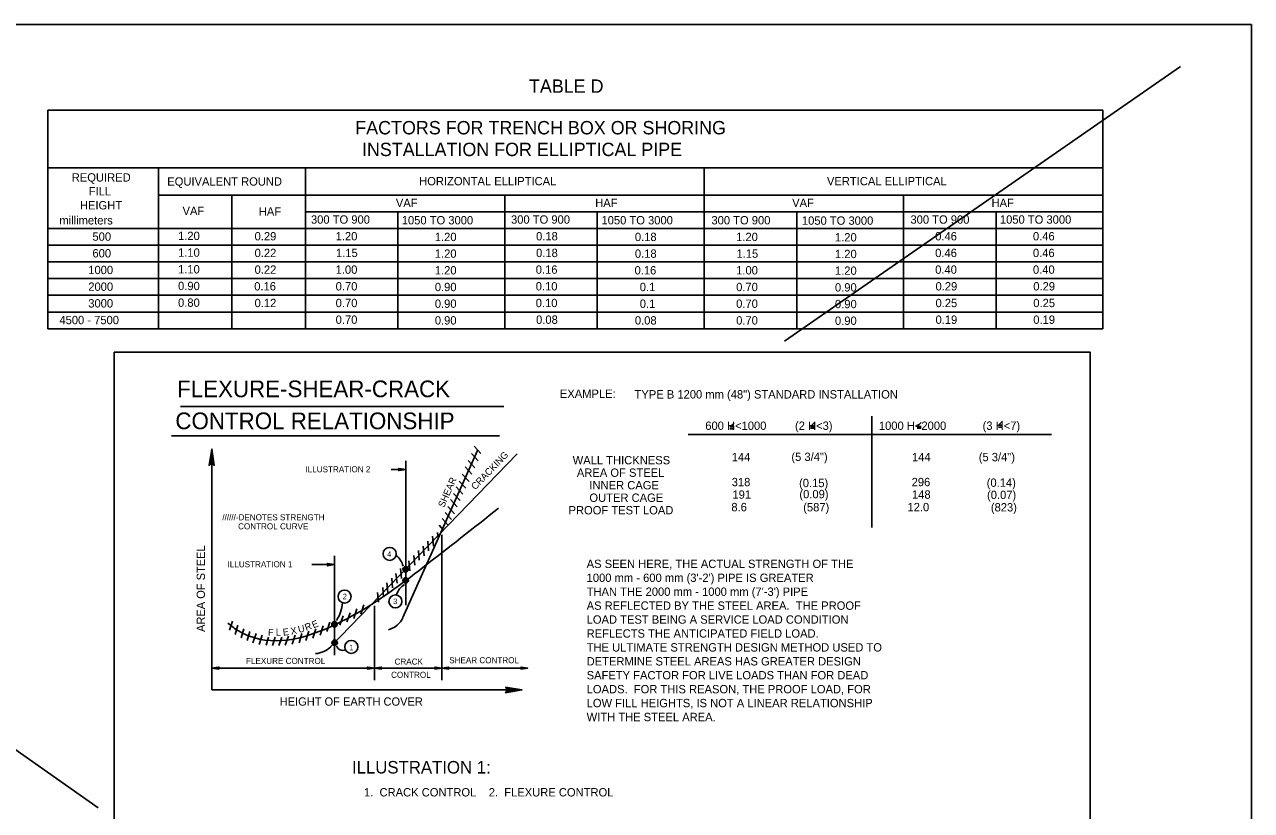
# Model space of a CAD drawing. Extents: x -22562 to -18409, y 3991 to 7171.
# Drawn here: x -21681.6 to -21240.8, y 6069.8 to 6352.4 of the extents above; entities that cross this region are included whole.
import ezdxf

# ---------------------------------------------------------------- set-up
doc = ezdxf.new("R2010")
doc.units = 0
for name, color, linetype in [('1', 7, 'Continuous'), ('2', 7, 'Continuous'), ('Default', 7, 'Continuous')]:
    doc.layers.add(name, color=color, linetype=linetype)

msp = doc.modelspace()

# ---------------------------------------------------------------- linework, layer by layer
at = {"layer": '1'}
for p, q in [((-22026.85, 6352.37), (-21240.85, 6352.37)), ((-21633.47, 6291.02), (-21294.22, 6291.02)), ((-21607.1, 6291.02), (-21607.1, 6243.02)), ((-21547.47, 6285.02), (-21547.47, 6243.02)), ((-21475.85, 6285.02), (-21475.85, 6243.02)), ((-21404.22, 6285.02), (-21404.22, 6243.02)), ((-21332.6, 6285.02), (-21332.6, 6243.02))]:
    msp.add_line(p, q, dxfattribs=at)
at = {"layer": '2'}
for p, q in [((-21240.85, 6352.37), (-21240.85, 5788.37)), ((-21673.22, 6321.56), (-21294.22, 6321.56)), ((-21673.22, 6321.56), (-21673.22, 6243.02)), ((-21294.22, 6321.56), (-21294.22, 6243.02)), ((-21673.22, 6300.83), (-21294.22, 6300.83)), ((-21633.47, 6300.83), (-21633.47, 6243.02)), ((-21580.72, 6300.83), (-21580.72, 6243.02)), ((-21437.47, 6300.83), (-21437.47, 6243.02)), ((-21509.1, 6291.02), (-21509.1, 6243.02)), ((-21365.85, 6291.02), (-21365.85, 6243.02)), ((-21580.72, 6285.02), (-21294.22, 6285.02)), ((-21673.22, 6279.02), (-21294.22, 6279.02)), ((-21673.22, 6273.02), (-21294.22, 6273.02)), ((-21673.22, 6267.02), (-21294.22, 6267.02)), ((-21673.22, 6261.02), (-21294.22, 6261.02)), ((-21673.22, 6255.02), (-21294.22, 6255.02)), ((-21673.22, 6249.02), (-21294.22, 6249.02)), ((-21673.22, 6243.02), (-21294.22, 6243.02)), ((-21509.44, 6215.02), (-21625.56, 6215.02)), ((-21377.17, 6211.56), (-21377.17, 6171.58)), ((-21426.7, 6209.2), (-21428.2, 6207.7)), ((-21428.2, 6207.7), (-21426.7, 6207.7)), ((-21428.2, 6207.08), (-21426.7, 6207.08)), ((-21397.73, 6209.37), (-21399.23, 6207.87)), ((-21399.23, 6207.87), (-21397.73, 6207.87)), ((-21399.23, 6207.25), (-21397.73, 6207.25)), ((-21359.46, 6209.33), (-21360.96, 6207.83)), ((-21360.96, 6207.83), (-21359.46, 6207.83)), ((-21360.96, 6207.21), (-21359.46, 6207.21)), ((-21330.24, 6209.8), (-21331.74, 6208.3)), ((-21331.74, 6208.3), (-21330.24, 6208.3)), ((-21331.74, 6207.68), (-21330.24, 6207.68)), ((-21510.94, 6204.52), (-21628.81, 6204.52)), ((-21443.19, 6204.96), (-21312.63, 6204.96)), ((-21614.31, 6199.77), (-21614.31, 6113.15)), ((-21571.56, 6128.77), (-21504.69, 6198.02)), ((-21545.69, 6139.15), (-21518.94, 6199.27)), ((-21521.06, 6198.15), (-21518.69, 6195.52)), ((-21520.06, 6200.77), (-21517.69, 6198.15)), ((-21544.69, 6195.52), (-21544.69, 6143.65)), ((-21523.31, 6193.4), (-21520.94, 6190.77)), ((-21522.19, 6195.65), (-21519.81, 6193.02)), ((-21549.94, 6192.4), (-21544.69, 6192.4)), ((-21524.44, 6190.77), (-21521.94, 6188.15)), ((-21526.56, 6186.15), (-21524.19, 6183.52)), ((-21525.44, 6188.27), (-21523.06, 6185.65)), ((-21528.56, 6181.65), (-21526.19, 6179.02)), ((-21527.56, 6183.77), (-21525.06, 6181.27)), ((-21530.56, 6176.9), (-21528.19, 6174.4)), ((-21529.56, 6179.15), (-21527.19, 6176.52)), ((-21532.69, 6172.4), (-21531.06, 6170.65)), ((-21531.56, 6174.77), (-21529.44, 6172.4)), ((-21536.69, 6166.65), (-21536.44, 6163.15)), ((-21535.06, 6168.4), (-21534.69, 6164.9)), ((-21533.31, 6169.77), (-21533.06, 6167.4)), ((-21531.69, 6168.9), (-21531.69, 6116.65)), ((-21540.06, 6163.27), (-21539.81, 6159.77)), ((-21538.44, 6164.9), (-21538.06, 6161.4)), ((-21578.44, 6158.27), (-21570.31, 6158.27)), ((-21570.31, 6161.4), (-21570.31, 6125.65)), ((-21543.56, 6159.52), (-21543.19, 6156.02)), ((-21541.81, 6161.52), (-21541.44, 6158.02)), ((-21549.69, 6153.4), (-21549.44, 6149.9)), ((-21548.19, 6155.02), (-21547.81, 6151.52)), ((-21546.56, 6156.77), (-21546.19, 6153.27)), ((-21552.94, 6150.02), (-21552.69, 6146.52)), ((-21551.44, 6151.65), (-21551.06, 6148.15)), ((-21554.81, 6148.15), (-21554.44, 6144.77)), ((-21564.69, 6140.9), (-21565.81, 6137.65)), ((-21562.19, 6142.27), (-21563.31, 6138.9)), ((-21559.69, 6143.77), (-21560.81, 6140.4)), ((-21555.94, 6143.4), (-21555.94, 6116.65)), ((-21606.94, 6137.9), (-21607.94, 6134.65)), ((-21604.94, 6136.4), (-21605.94, 6133.15)), ((-21574.31, 6136.27), (-21575.44, 6132.9)), ((-21571.94, 6137.52), (-21573.06, 6134.15)), ((-21567.19, 6139.77), (-21568.31, 6136.4)), ((-21602.81, 6135.15), (-21603.81, 6131.9)), ((-21600.69, 6134.15), (-21601.69, 6130.9)), ((-21598.44, 6133.4), (-21599.56, 6130.15)), ((-21596.19, 6132.9), (-21597.31, 6129.52)), ((-21593.94, 6132.15), (-21594.81, 6129.27)), ((-21591.56, 6132.15), (-21592.56, 6129.15)), ((-21589.19, 6132.15), (-21590.31, 6129.15)), ((-21586.81, 6132.52), (-21587.94, 6129.27)), ((-21584.44, 6132.9), (-21585.44, 6129.65)), ((-21581.94, 6133.4), (-21582.94, 6130.15)), ((-21579.44, 6134.27), (-21580.56, 6130.9)), ((-21576.94, 6135.15), (-21578.06, 6131.77)), ((-21614.31, 6121.02), (-21555.94, 6121.02)), ((-21555.94, 6121.02), (-21531.69, 6121.02)), ((-21531.69, 6121.02), (-21500.81, 6121.02)), ((-21614.31, 6113.15), (-21502.94, 6113.15))]:
    msp.add_line(p, q, dxfattribs=at)
for points in [[(-21615.06, 6194.15), (-21614.69, 6194.27), (-21614.31, 6199.77), (-21615.06, 6194.15), (-21615.31, 6193.9), (-21614.31, 6199.77), (-21614.06, 6194.4), (-21613.69, 6194.15), (-21614.31, 6199.77), (-21613.44, 6193.9), (-21613.69, 6194.15)], [(-21547.06, 6192.65), (-21547.06, 6192.52), (-21544.69, 6192.4), (-21547.06, 6192.65), (-21547.19, 6192.77), (-21544.69, 6192.4), (-21547.06, 6192.27), (-21547.06, 6192.02), (-21544.69, 6192.4), (-21547.19, 6192.02), (-21547.06, 6192.02)], [(-21572.69, 6158.52), (-21572.56, 6158.4), (-21570.31, 6158.27), (-21572.69, 6158.52), (-21572.81, 6158.65), (-21570.31, 6158.27), (-21572.56, 6158.15), (-21572.69, 6157.9), (-21570.31, 6158.27), (-21572.81, 6157.77), (-21572.69, 6157.9)], [(-21611.94, 6120.77), (-21612.06, 6120.9), (-21614.31, 6121.02), (-21611.94, 6120.77), (-21611.81, 6120.65), (-21614.31, 6121.02), (-21612.06, 6121.15), (-21611.94, 6121.4), (-21614.31, 6121.02), (-21611.81, 6121.4), (-21611.94, 6121.4)], [(-21558.31, 6121.4), (-21558.19, 6121.15), (-21555.94, 6121.02), (-21558.31, 6121.4), (-21558.44, 6121.4), (-21555.94, 6121.02), (-21558.19, 6120.9), (-21558.31, 6120.77), (-21555.94, 6121.02), (-21558.44, 6120.65), (-21558.31, 6120.77)], [(-21553.56, 6120.77), (-21553.69, 6120.9), (-21555.94, 6121.02), (-21553.56, 6120.77), (-21553.44, 6120.65), (-21555.94, 6121.02), (-21553.69, 6121.15), (-21553.56, 6121.4), (-21555.94, 6121.02), (-21553.44, 6121.4), (-21553.56, 6121.4)], [(-21534.06, 6121.4), (-21533.94, 6121.15), (-21531.69, 6121.02), (-21534.06, 6121.4), (-21534.19, 6121.4), (-21531.69, 6121.02), (-21533.94, 6120.9), (-21534.06, 6120.77), (-21531.69, 6121.02), (-21534.19, 6120.65), (-21534.06, 6120.77)], [(-21529.31, 6120.77), (-21529.44, 6120.9), (-21531.69, 6121.02), (-21529.31, 6120.77), (-21529.19, 6120.65), (-21531.69, 6121.02), (-21529.44, 6121.15), (-21529.31, 6121.4), (-21531.69, 6121.02), (-21529.19, 6121.4), (-21529.31, 6121.4)], [(-21503.19, 6121.4), (-21503.19, 6121.15), (-21500.81, 6121.02), (-21503.19, 6121.4), (-21503.31, 6121.4), (-21500.81, 6121.02), (-21503.19, 6120.9), (-21503.19, 6120.77), (-21500.81, 6121.02), (-21503.31, 6120.65), (-21503.19, 6120.77)], [(-21508.56, 6113.9), (-21508.31, 6113.4), (-21502.94, 6113.15), (-21508.56, 6113.9), (-21508.81, 6114.15), (-21502.94, 6113.15), (-21508.31, 6112.9), (-21508.56, 6112.52), (-21502.94, 6113.15), (-21508.81, 6112.15), (-21508.56, 6112.52)]]:
    msp.add_lwpolyline(points, dxfattribs=at)
for centre, radius in [((-21550.44, 6162.08), 2.35), ((-21544.72, 6156.54), 0.976), ((-21544.68, 6152.55), 0.976), ((-21544.72, 6156.54), 0.804), ((-21544.68, 6152.55), 0.778), ((-21544.72, 6156.54), 0.6), ((-21544.72, 6156.54), 0.4), ((-21544.72, 6156.54), 0.175), ((-21566.63, 6146.73), 2.35), ((-21544.68, 6152.55), 0.574), ((-21544.68, 6152.55), 0.326), ((-21544.68, 6152.55), 0.147), ((-21548.37, 6145.01), 2.35), ((-21570.28, 6136.78), 0.976), ((-21570.28, 6136.78), 0.826), ((-21570.28, 6136.78), 0.6), ((-21570.28, 6136.78), 0.38), ((-21570.28, 6136.78), 0.189), ((-21570.21, 6130.15), 0.976), ((-21570.21, 6130.15), 0.755), ((-21570.21, 6130.15), 0.538), ((-21570.21, 6130.15), 0.302), ((-21570.21, 6130.15), 0.14), ((-21564.22, 6128.63), 2.35)]:
    msp.add_circle(centre, radius, dxfattribs=at)
for centre, radius, start, end in [((-21552.67, 6155.84), 7.29, 14.6383, 49.5671), ((-21541.42, 6145.31), 6.88, 122.2525, 163.6384), ((-21581.55, 6145.71), 14.19, 327.6246, 355.0838), ((-21553.08, 6142.64), 8.17, 286.1711, 334.5647), ((-21577.94, 6135.49), 9.32, 275.4083, 313.415), ((-21567.24, 6129.86), 2.46, 199.0809, 292.6529)]:
    msp.add_arc(centre, radius, start, end, dxfattribs=at)
msp.add_spline([(-21608.56, 6137.15), (-21604.81, 6134.4), (-21589.19, 6130.9), (-21575.56, 6134.27), (-21550.44, 6148.27), (-21538.56, 6157.15), (-21511.31, 6178.52)], degree=3, dxfattribs=at)
at = {"layer": 'Default'}
for p, q in [((-22043.04, 6343.98), (-21655.17, 6070.76)), ((-21408.57, 6238.49), (-21266.39, 6337.22))]:
    msp.add_line(p, q, dxfattribs=at)
msp.add_lwpolyline([(-21649.46, 6234.6), (-21298.83, 6234.6), (-21298.83, 5958.1), (-21649.46, 5958.1)], close=True, dxfattribs=at)

# ---------------------------------------------------------------- texts
at = {"layer": '1'}
for s, height, p in [('TABLE D', 4.806, (-21500.41, 6327.82)), ('FACTORS FOR TRENCH BOX OR SHORING', 4.8057, (-21562.8, 6312.88)), ('INSTALLATION FOR ELLIPTICAL PIPE', 4.8057, (-21560.39, 6305.07)), ('EQUIVALENT ROUND', 3, (-21630.35, 6294.45)), ('HORIZONTAL ELLIPTICAL', 3, (-21539.85, 6294.57)), ('VERTICAL ELLIPTICAL', 3, (-21393.35, 6294.57)), ('VAF', 3, (-21624.85, 6283.89)), ('HAF', 3, (-21597.47, 6283.64)), ('VAF', 3, (-21548.22, 6286.77)), ('HAF', 3, (-21476.6, 6286.77)), ('VAF', 3, (-21405.85, 6286.77)), ('HAF', 3, (-21334.22, 6286.77)), ('300 TO 900', 3, (-21578.72, 6280.77)), ('1050 TO 3000', 3, (-21546.1, 6280.52)), ('300 TO 900', 3, (-21506.85, 6280.77)), ('1050 TO 3000', 3, (-21474.35, 6280.52)), ('300 TO 900', 3, (-21434.85, 6280.52)), ('1050 TO 3000', 3, (-21402.35, 6280.39)), ('300 TO 900', 3, (-21363.35, 6280.77)), ('1050 TO 3000', 3, (-21331.22, 6280.77)), ('1.20', 3, (-21626.47, 6274.89)), ('0.29', 3, (-21598.97, 6274.77)), ('1.20', 3, (-21569.85, 6274.77)), ('1.20', 3, (-21534.22, 6274.52)), ('0.18', 3, (-21497.85, 6274.77)), ('0.18', 3, (-21462.35, 6274.52)), ('1.20', 3, (-21425.97, 6274.52)), ('1.20', 3, (-21390.47, 6274.39)), ('0.46', 3, (-21354.47, 6274.77)), ('0.46', 3, (-21319.35, 6274.77)), ('1.10', 3, (-21626.47, 6268.89)), ('0.22', 3, (-21598.97, 6268.77)), ('1.15', 3, (-21569.72, 6268.77)), ('1.20', 3, (-21534.22, 6268.52)), ('0.18', 3, (-21497.85, 6268.77)), ('0.18', 3, (-21462.35, 6268.52)), ('1.15', 3, (-21425.85, 6268.52)), ('1.20', 3, (-21390.47, 6268.39)), ('0.46', 3, (-21354.47, 6268.77)), ('0.46', 3, (-21319.35, 6268.77)), ('1.10', 3, (-21626.47, 6262.89)), ('0.22', 3, (-21598.97, 6262.77)), ('1.00', 3, (-21569.85, 6262.77)), ('1.20', 3, (-21534.22, 6262.52)), ('0.16', 3, (-21497.97, 6262.77)), ('0.16', 3, (-21462.47, 6262.52)), ('1.00', 3, (-21425.97, 6262.52)), ('1.20', 3, (-21390.47, 6262.39)), ('0.40', 3, (-21354.47, 6262.77)), ('0.40', 3, (-21319.35, 6262.77)), ('0.90', 3, (-21626.47, 6256.89)), ('0.16', 3, (-21599.1, 6256.77)), ('0.70', 3, (-21569.85, 6256.77)), ('0.90', 3, (-21534.22, 6256.52)), ('0.10', 3, (-21497.97, 6256.77)), ('0.1', 3, (-21460.6, 6256.52)), ('0.70', 3, (-21425.97, 6256.52)), ('0.90', 3, (-21390.47, 6256.39)), ('0.29', 3, (-21354.35, 6256.77)), ('0.29', 3, (-21319.22, 6256.77)), ('0.80', 3, (-21626.47, 6250.89)), ('0.12', 3, (-21598.97, 6250.77)), ('0.70', 3, (-21569.85, 6250.77)), ('0.90', 3, (-21534.22, 6250.52)), ('0.10', 3, (-21497.97, 6250.77)), ('0.1', 3, (-21460.6, 6250.52)), ('0.70', 3, (-21425.97, 6250.52)), ('0.90', 3, (-21390.47, 6250.39)), ('0.25', 3, (-21354.35, 6250.77)), ('0.25', 3, (-21319.22, 6250.77)), ('0.70', 3, (-21569.85, 6244.77)), ('0.90', 3, (-21534.22, 6244.52)), ('0.08', 3, (-21497.85, 6244.77)), ('0.08', 3, (-21462.35, 6244.52)), ('0.70', 3, (-21425.97, 6244.52)), ('0.90', 3, (-21390.47, 6244.39)), ('0.19', 3, (-21354.35, 6244.77)), ('0.19', 3, (-21319.22, 6244.77))]:
    msp.add_text(s, height=height, dxfattribs=at).set_placement(p)
at = {"layer": '2'}
for s, height, p in [('REQUIRED', 3, (-21664.66, 6295.91)), ('FILL', 3, (-21658.58, 6290.91)), ('HEIGHT', 3, (-21661.72, 6285.9)), ('millimeters', 3, (-21669.1, 6280.49)), ('500', 3, (-21657.22, 6274.64)), ('600', 3, (-21657.22, 6268.64)), ('1000', 3, (-21658.72, 6262.64)), ('2000', 3, (-21658.72, 6256.64)), ('3000', 3, (-21658.72, 6250.64)), ('4500 - 7500', 3, (-21669.1, 6244.64)), (' FLEXURE-SHEAR-CRACK', 6, (-21629.06, 6218.4)), ('EXAMPLE:', 3, (-21489.31, 6218.15)), ('TYPE B 1200 mm (48") STANDARD INSTALLATION', 3, (-21462.47, 6217.93)), ('CONTROL RELATIONSHIP', 6, (-21627.44, 6206.9)), ('600 H<1000', 3, (-21437.07, 6206.65)), ('(2 H<3)', 3, (-21404.83, 6206.65)), (' 1000 H<2000', 3, (-21375.81, 6206.65)), ('(3 H<7)', 3, (-21337.43, 6206.66)), ('WALL THICKNESS', 3, (-21484.69, 6194.27)), ('144', 3, (-21427.56, 6195.4)), ('(5 3/4")', 3, (-21406.12, 6195.48)), ('144', 3, (-21362.8, 6195.4)), ('(5 3/4")', 3, (-21338.82, 6195.39)), ('ILLUSTRATION 2', 2.178, (-21580.69, 6191.4)), ('AREA OF STEEL', 3, (-21483.19, 6189.77)), ('318', 3, (-21427.56, 6186.4)), ('(0.15)', 3, (-21403.37, 6186.07)), ('296', 3, (-21362.92, 6186.4)), ('(0.14)', 3, (-21335.96, 6186.18)), ('INNER CAGE', 3, (-21478.69, 6185.27)), ('191', 3, (-21427.31, 6181.9)), ('(0.09)', 3, (-21403.26, 6182.07)), ('148', 3, (-21362.8, 6181.9)), ('(0.07)', 3, (-21335.84, 6181.79)), ('OUTER CAGE', 3, (-21478.69, 6180.77)), ('8.6', 3, (-21427.69, 6177.4)), ('(587)', 3, (-21401.88, 6177.35)), ('12.0', 3, (-21364.42, 6177.4)), ('(823)', 3, (-21334.47, 6177.33)), ('//////-DENOTES STRENGTH', 2.178, (-21610.56, 6174.15)), ('PROOF TEST LOAD', 3, (-21486.19, 6176.27)), ('       CONTROL CURVE', 2.178, (-21610.56, 6170.9)), ('4', 1.98, (-21551.31, 6161.02)), ('ILLUSTRATION 1', 2.178, (-21608.69, 6157.27)), ('AS SEEN HERE, THE ACTUAL STRENGTH OF THE', 3, (-21479.68, 6157)), ("1000 mm - 600 mm (3'-2') PIPE IS GREATER", 3, (-21479.68, 6151.99)), ("THAN THE 2000 mm - 1000 mm (7'-3') PIPE", 3, (-21479.68, 6146.99)), ('2', 1.98, (-21567.31, 6145.77)), ('3', 1.98, (-21549.19, 6144.02)), ('AS REFLECTED BY THE STEEL AREA.  THE PROOF', 3, (-21479.68, 6141.98)), ('LOAD TEST BEING A SERVICE LOAD CONDITION', 3, (-21479.68, 6136.98)), ('REFLECTS THE ANTICIPATED FIELD LOAD.', 3, (-21479.68, 6131.97)), ('1', 1.98, (-21564.94, 6127.4)), ('THE ULTIMATE STRENGTH DESIGN METHOD USED TO', 3, (-21479.68, 6126.97)), ('FLEXURE CONTROL', 2.178, (-21602.06, 6122.52)), ('CRACK', 2.178, (-21548.69, 6122.27)), ('SHEAR CONTROL', 2.178, (-21529.06, 6122.77)), ('DETERMINE STEEL AREAS HAS GREATER DESIGN', 3, (-21479.68, 6121.96)), ('CONTROL', 2.178, (-21549.94, 6117.52)), ('SAFETY FACTOR FOR LIVE LOADS THAN FOR DEAD', 3, (-21479.68, 6116.96)), ('LOADS.  FOR THIS REASON, THE PROOF LOAD, FOR', 3, (-21479.68, 6111.95)), ('HEIGHT OF EARTH COVER', 2.97, (-21589.94, 6107.52)), ('LOW FILL HEIGHTS, IS NOT A LINEAR RELATIONSHIP', 3, (-21479.68, 6106.95)), ('WITH THE STEEL AREA.', 3, (-21479.68, 6101.94)), ('ILLUSTRATION 1:', 4.5, (-21563.97, 6083.13)), ('      1.  CRACK CONTROL    2.  FLEXURE CONTROL', 3, (-21566.35, 6074.88))]:
    msp.add_text(s, height=height, dxfattribs=at).set_placement(p)
for s, height, rotation, p in [('CRACKING', 2.475, 46.0195, (-21519.69, 6184.9)), ('SHEAR', 2.475, 65.997, (-21530.94, 6178.52)), ('AREA OF STEEL', 2.97, 90, (-21616.81, 6134.02)), ('X', 2.48, 9.8509, (-21585.81, 6133.02)), ('U', 2.48, 13.4055, (-21583.06, 6133.65)), ('R', 2.47, 19.0594, (-21580.44, 6134.4)), ('E', 2.48, 22.5964, (-21577.81, 6135.27)), ('F', 2.47, 357.977, (-21594.19, 6132.65)), ('L', 2.48, 1.5168, (-21591.31, 6132.65)), ('E', 2.48, 6.7323, (-21588.69, 6132.65))]:
    msp.add_text(s, height=height, rotation=rotation, dxfattribs=at).set_placement(p)

doc.saveas('drawing.dxf')
